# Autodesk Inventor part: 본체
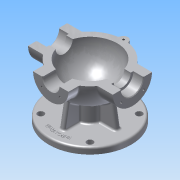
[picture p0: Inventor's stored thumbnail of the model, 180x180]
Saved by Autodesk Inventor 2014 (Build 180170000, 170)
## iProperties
Created: 2015-12
Part Number: 본체
Material: 알루미늄 6061
Document SubType Name: Modeling
Designer: mduedu
Density: 2.71 g/cm^3
Mass: 966.367 g
Surface Area: 788.536 cm^2
Volume: 356.593 cm^3
Appearance: 알루미늄 - 평지
Author: mduedu
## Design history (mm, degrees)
sketch "스케치1"
  geometry: L1 (-53, 0)-(53, 0); A1 r 53 centre (0, 0) between (53, 0) and (-53, 0); 2 further points
  constraints: 2 coincident, 2 end point, 2 point on circle, 1 centre point, 1 horizontal, 1 midpoint
  dimensions: "d0" = 53 radius of A1
revolve "회전1" sketch "스케치1" stored, may be unused: angle "d2" = 90 deg
feature "쉘1" dims "d11" = 10
node "작업 평면1"
sketch "스케치2"
  geometry: C1 r 31 at (0, 0); 1 further point
  constraints: 1 centre point, 1 coincident
  dimensions: "d4" = 62 diameter of C1
extrude "돌출1" join sketch "스케치2" stored distance "d5" = 10; taper "d6" = 0 deg
node "작업 평면2"
sketch "스케치3"
  geometry: C1 r 28 at (0, 0); 1 further point
  constraints: 1 centre point, 1 coincident
  dimensions: "d8" = 56 diameter of C1
extrude "돌출2" join sketch "스케치3" stored distance "d9" = 10; taper "d10" = 0 deg
hole "구멍1" diameter "d14" = 35; stored, may be unused: countersink angle "d18" = 90 deg, drill point angle "d20" = 0 deg; dims "d12" = 10, "d13" = 10, "d15" = 6, "d16" = 4, "d17" = 2, "d19" = 16
hole "구멍2" diameter "d23" = 27; stored, may be unused: countersink angle "d27" = 90 deg, drill point angle "d29" = 0 deg; dims "d21" = 10, "d22" = 10, "d24" = 6, "d25" = 4, "d26" = 2, "d28" = 16
fillet "모깎기1" dims "d30" = 0.3
hole "구멍3" diameter "d33" = 26; stored, may be unused: countersink angle "d37" = 90 deg, drill point angle "d39" = 0 deg; dims "d31" = 10, "d32" = 10, "d34" = 6, "d35" = 4, "d36" = 2, "d38" = 16
chamfer "모따기1" distance "d40" = 1; stored, may be unused: second distance "d41" = 2, angle "d42" = 45 deg
sketch "스케치4"
  geometry: L1 (0, 0)-(0, -25); L2 (0, 0)-(-17.678, -17.678); A1 r 25 centre (0, 0) between (-17.678, -17.678) and (0, -25); 1 further point
  constraints: 4 end point, 2 point on circle, 1 centre point, 1 coincident, 1 vertical
  dimensions: "d43" = 50 diameter of A1; "d47" = 45 deg angle of L1 L2
hole "구멍4" sketch "스케치4" at (-17.678, -17.678) diameter "d49" = 3.242; stored, may be unused: countersink angle "d53" = 90 deg, drill point angle "d55" = 118 deg; dims "d50" = 11, "d51" = 4, "d52" = 2, "d54" = 13
sketch "스케치5"
  geometry: L1 (0, 0)-(0, -20); L2 (0, 0)-(-14.142, -14.142); A1 r 20 centre (0, 0) between (0, -20) and (-14.142, -14.142); 2 further points
  constraints: 4 end point, 2 coincident, 2 point on circle, 1 centre point, 1 vertical
  dimensions: "d59" = 40 diameter of A1; "d65" = 45 deg angle of L1 L2
hole "구멍5" sketch "스케치5" at (-14.142, -14.142) diameter "d67" = 3.242; stored, may be unused: countersink angle "d71" = 90 deg, drill point angle "d73" = 118 deg; dims "d68" = 8, "d69" = 4, "d70" = 2, "d72" = 10
node "작업 평면3"
sketch "스케치6"
  geometry: C1 r 65 at (0, 0); 1 further point
  constraints: 1 centre point, 1 coincident
  dimensions: "d78" = 130 diameter of C1
extrude "돌출3" join sketch "스케치6" distance "d80" = 10; taper "d81" = 0 deg
sketch "스케치7"
  geometry: C1 r 20 at (0, 0); 1 further point
  constraints: 1 centre point, 1 coincident
  dimensions: "d82" = 40 diameter of C1
extrude "돌출4" join sketch "스케치7" stored distance "d84" = 10; taper "d85" = 0 deg
sketch "스케치8"
  geometry: 2 further points
  constraints: 1 coincident
hole "구멍6" sketch "스케치8" at (0, 0) diameter "d86" = 20; stored, may be unused: countersink angle "d90" = 90 deg, drill point angle "d92" = 118 deg; dims "d87" = 7, "d88" = 40, "d89" = 5, "d91" = 10
fillet "모깎기2" dims "d93" = 0.3
sketch "스케치9"
  geometry: L1 (65, -75)-(-65, -75) reference; L2 (-45, -75)-(-38.245, -36.692); A1 r 53 centre (0, 0) between (42.988, 31) and (42.988, -31) reference; 1 further point
  constraints: 2 end point, 1 point on circle, 1 point on line
  dimensions: "d94" = 45 horizontal distance of L2.start point (0, 0); "d95" = 80 deg angle of L2 L1
feature "리브1" sketch "스케치9" dims "d96" = 1, "d97" = 8, "d98" = 0, "d99" = 0, "d100" = 1, "d101" = 1
sketch "스케치10"
  geometry: L1 (0, 0)-(0, -55); L2 (0, 0)-(-38.891, -38.891); A1 r 55 centre (0, 0) between (0, -55) and (-38.891, -38.891); 2 further points
  constraints: 4 end point, 2 coincident, 2 point on circle, 1 centre point, 1 vertical
  dimensions: "d105" = 110 diameter of A1; "d107" = 45 deg angle of L1 L2
hole "구멍7" sketch "스케치10" at (-38.891, -38.891) diameter "d109" = 10; stored, may be unused: countersink angle "d113" = 90 deg, drill point angle "d115" = 118 deg; dims "d110" = 7, "d111" = 40, "d112" = 5, "d114" = 10
fillet "모깎기3" dims "d120" = 3
fillet "모깎기4" dims "d121" = 3, "d122" = 3
fillet "모깎기5" dims "d123" = 3
fillet "모깎기6" dims "d124" = 3
sketch "스케치11"
  geometry: C1 r 5 at (-38.891, 38.891) reference; C2 r 5 at (38.891, 38.891) reference; C3 r 5 at (38.891, -38.891) reference; C4 r 5 at (-38.891, -38.891) reference; C5 r 20 at (0, 0) reference; C6 r 65 at (0, 0) reference; 1 further point
  constraints: 3 other
feature "엠보싱1" sketch "스케치11" dims "d125" = 0.5, "d126" = 0
sketch "스케치12"
  geometry: L1 (0, 100)-(0, -100); L2 (0, 100)-(100, 100); L3 (100, 100)-(100, -100); L4 (100, -100)-(0, -100); 2 further points
  constraints: 8 end point, 3 perpendicular, 1 coincident, 1 midpoint, 1 vertical
  dimensions: "d127" = 200 distance of L2.end L3.end; "d129" = 100 distance between parallel lines of L1 L3
extrude "돌출5" cut sketch "스케치12" stored distance "d130" = 10; taper "d131" = 0 deg
sketch "스케치13"
  geometry: C1 r 7 at (0, 53); A1 r 53 centre (0, 0) between (42.113, 32.179) and (-42.113, 32.179) reference; 1 further point
  constraints: 1 centre point, 1 point on circle
  dimensions: "d132" = 14 diameter of C1
extrude "돌출6" join sketch "스케치13" distance "d134" = 15; taper "d135" = 0 deg
hole "구멍8" diameter "d139" = 3.242; stored, may be unused: countersink angle "d143" = 90 deg, drill point angle "d145" = 118 deg; dims "d140" = 8, "d141" = 4, "d142" = 2, "d144" = 10, "d148" = 10, "d149" = 10
fillet "모깎기7" dims "d146" = 3
fillet "모깎기8" dims "d147" = 3
node "솔리드1"
mirror "대칭1"
mirror "대칭2"
pattern_circular "원형 패턴1" dims angle "d57" = 360 deg
mirror "대칭3"
pattern_circular "원형 패턴2" dims angle "d75" = 360 deg
pattern_circular "원형 패턴3" dims angle "d103" = 360 deg
pattern_circular "원형 패턴4" dims angle "d118" = 360 deg
node "투영된 루프1"
other parameters: "d3" = 67, "d7" = 62, "d77" = -85
